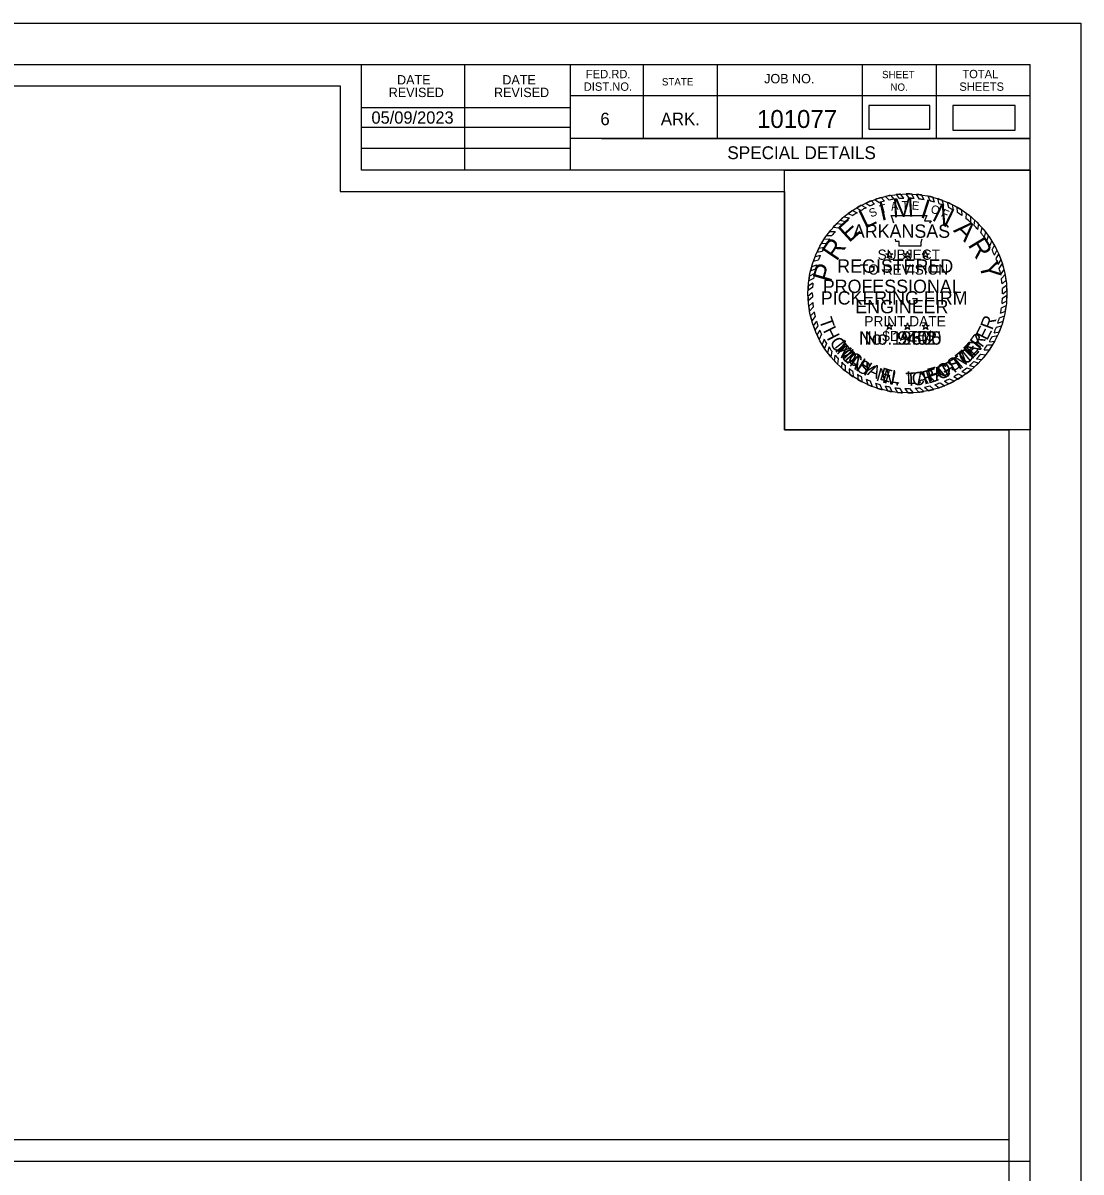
# Model space of a CAD drawing. Extents: x 1372039 to 1372773, y 376713 to 376926.
# Drawn here: x 1372673.7 to 1372772.8, y 376818.4 to 376926 of the extents above; entities that cross this region are included whole.
import ezdxf

# ---------------------------------------------------------------- set-up
doc = ezdxf.new("R2010")
doc.units = 0
for name, color, linetype in [('Default', 7, 'Continuous'), ('R_Border', 7, 'Continuous'), ('R_Border Notes', 7, 'Continuous'), ('R_Border Plan-Plan', 7, 'Continuous'), ('R_No Plot', 7, 'Continuous'), ('R_Revision Date Text', 7, 'Continuous'), ('STAMP_PE_CRAFTON', 7, 'Continuous'), ('STAMP_PE_FOSTER', 7, 'Continuous'), ('STAMP_PE_SEAL-INFO', 7, 'Continuous'), ('STAMP_PE_TAEGTMEYER', 7, 'Continuous'), ('STAMP_PE_TXT', 7, 'Continuous'), ('STAMP_PRELIMINARY', 7, 'Continuous')]:
    doc.layers.add(name, color=color, linetype=linetype)

msp = doc.modelspace()

# ---------------------------------------------------------------- linework, layer by layer
at = {"layer": 'Default'}
for points in [[(1372752.89, 376916.07), (1372758.6, 376916.07), (1372758.6, 376918.26), (1372752.89, 376918.26)], [(1372760.76, 376915.96), (1372766.59, 376915.96), (1372766.59, 376918.27), (1372760.76, 376918.27)]]:
    msp.add_lwpolyline(points, close=True, dxfattribs=at)
at = {"layer": 'R_Border'}
for p, q in [((1372451.83, 376922.11), (1372768.01, 376922.11)), ((1372705.37, 376912.23), (1372705.37, 376922.11)), ((1372715.05, 376912.23), (1372715.05, 376922.11)), ((1372724.91, 376922.11), (1372724.91, 376912.23)), ((1372731.75, 376922.11), (1372731.75, 376915.17)), ((1372738.69, 376922.11), (1372738.69, 376915.17)), ((1372752.27, 376922.11), (1372752.27, 376915.17)), ((1372759.21, 376922.11), (1372759.21, 376915.17)), ((1372768.01, 376716.65), (1372768.01, 376922.11)), ((1372768.01, 376919.17), (1372724.91, 376919.17)), ((1372768.01, 376919.19), (1372768.01, 376919.19)), ((1372705.37, 376918.09), (1372724.91, 376918.09)), ((1372705.37, 376916.23), (1372724.91, 376916.23)), ((1372768.01, 376915.17), (1372724.91, 376915.17)), ((1372727.87, 376915.17), (1372768.01, 376915.17)), ((1372705.37, 376914.29), (1372724.91, 376914.29)), ((1372768.01, 376912.23), (1372705.37, 376912.23))]:
    msp.add_line(p, q, dxfattribs=at)
at = {"layer": 'R_Border Plan-Plan'}
msp.add_line((1372451.83, 376819.38), (1372768.01, 376819.38), dxfattribs=at)
at = {"layer": 'R_No Plot'}
msp.add_line((1372439.43, 376926), (1372772.76, 376926), dxfattribs=at)
for points in [[(1372439.42, 376926), (1372772.76, 376926), (1372772.76, 376712.66), (1372439.42, 376712.66)], [(1372453.83, 376920.11), (1372703.37, 376920.11), (1372703.37, 376910.23), (1372720.91, 376910.23), (1372745.01, 376910.23), (1372745.01, 376887.89), (1372766.01, 376887.89), (1372766.01, 376718.65), (1372453.83, 376718.65)], [(1372766.01, 376821.38), (1372453.83, 376821.38), (1372453.83, 376920.11), (1372703.37, 376920.11), (1372703.37, 376910.23), (1372720.91, 376910.23), (1372745.01, 376910.23), (1372745.01, 376887.89), (1372766.01, 376887.89)], [(1372745.01, 376912.23), (1372768.01, 376912.23), (1372768.01, 376887.89), (1372745.01, 376887.89)]]:
    msp.add_lwpolyline(points, close=True, dxfattribs=at)
at = {"layer": 'STAMP_PE_SEAL-INFO'}
for p, q in [((1372752.62, 376909.14), (1372753.01, 376908.86)), ((1372753.12, 376909.36), (1372753.42, 376909.03)), ((1372753.47, 376909.48), (1372753.85, 376909.18)), ((1372754.06, 376909.67), (1372754.35, 376909.32)), ((1372754.45, 376909.76), (1372754.81, 376909.42)), ((1372754.93, 376909.86), (1372755.23, 376909.49)), ((1372755.45, 376909.93), (1372755.73, 376909.55)), ((1372756.18, 376909.58), (1372755.87, 376909.97)), ((1372756.68, 376909.58), (1372756.4, 376909.99)), ((1372757.14, 376909.56), (1372756.88, 376909.99)), ((1372757.65, 376909.51), (1372757.35, 376909.95)), ((1372758.07, 376909.45), (1372757.81, 376909.9)), ((1372758.63, 376909.33), (1372758.46, 376909.79)), ((1372759.04, 376909.22), (1372758.88, 376909.69)), ((1372759.49, 376909.07), (1372759.35, 376909.55)), ((1372759.91, 376908.91), (1372759.76, 376909.41)), ((1372760.37, 376908.71), (1372760.26, 376909.2)), ((1372750.93, 376908.17), (1372751.39, 376907.96)), ((1372751.35, 376908.43), (1372751.79, 376908.23)), ((1372751.74, 376908.68), (1372752.17, 376908.45)), ((1372752.19, 376908.93), (1372752.65, 376908.7)), ((1372760.81, 376908.48), (1372760.73, 376908.99)), ((1372761.2, 376908.25), (1372761.16, 376908.75)), ((1372761.63, 376907.96), (1372761.6, 376908.48)), ((1372762, 376907.7), (1372762.03, 376908.18)), ((1372749.87, 376907.22), (1372750.42, 376907.17)), ((1372750.21, 376907.54), (1372750.67, 376907.4)), ((1372750.55, 376907.84), (1372751.08, 376907.74)), ((1372754.99, 376907.96), (1372758.33, 376907.96)), ((1372755.11, 376907.65), (1372754.99, 376907.96)), ((1372755.21, 376907.36), (1372755.11, 376907.65)), ((1372755.22, 376907.24), (1372755.21, 376907.36)), ((1372758.33, 376907.96), (1372758.1, 376907.47)), ((1372758.1, 376907.47), (1372758.74, 376907.47)), ((1372758.74, 376907.47), (1372758.59, 376907.24)), ((1372762.44, 376907.33), (1372762.46, 376907.85)), ((1372762.75, 376907.03), (1372762.82, 376907.53)), ((1372763.11, 376906.66), (1372763.18, 376907.19)), ((1372748.93, 376906.09), (1372749.43, 376906.09)), ((1372749.21, 376906.46), (1372749.75, 376906.48)), ((1372749.55, 376906.87), (1372750.07, 376906.83)), ((1372763.39, 376906.34), (1372763.52, 376906.81)), ((1372763.71, 376905.93), (1372763.85, 376906.43)), ((1372763.93, 376905.61), (1372764.11, 376906.07)), ((1372748.22, 376904.92), (1372748.71, 376904.99)), ((1372748.45, 376905.35), (1372748.94, 376905.37)), ((1372748.69, 376905.75), (1372749.21, 376905.78)), ((1372755.41, 376905.53), (1372755.38, 376905.75)), ((1372755.72, 376905.53), (1372755.41, 376905.53)), ((1372755.72, 376905.1), (1372755.72, 376905.53)), ((1372757.75, 376905.1), (1372755.72, 376905.1)), ((1372757.77, 376905.44), (1372757.75, 376905.1)), ((1372757.85, 376905.75), (1372757.77, 376905.44)), ((1372764.24, 376905.11), (1372764.42, 376905.6)), ((1372764.44, 376904.75), (1372764.67, 376905.19)), ((1372747.69, 376903.69), (1372748.18, 376903.83)), ((1372747.84, 376904.1), (1372748.35, 376904.25)), ((1372748.03, 376904.53), (1372748.53, 376904.64)), ((1372764.67, 376904.26), (1372764.9, 376904.75)), ((1372764.81, 376903.93), (1372765.07, 376904.36)), ((1372765, 376903.38), (1372765.28, 376903.85)), ((1372747.43, 376902.78), (1372747.9, 376902.98)), ((1372747.54, 376903.19), (1372748.01, 376903.36)), ((1372765.11, 376903.01), (1372765.41, 376903.46)), ((1372765.25, 376902.45), (1372765.56, 376902.9)), ((1372747.65, 376901.64), (1372747.22, 376901.36)), ((1372747.71, 376902.08), (1372747.27, 376901.86)), ((1372747.8, 376902.54), (1372747.33, 376902.29)), ((1372765.31, 376902.07), (1372765.67, 376902.43)), ((1372765.38, 376901.56), (1372765.75, 376901.9)), ((1372747.62, 376901.22), (1372747.19, 376900.96)), ((1372747.6, 376900.73), (1372747.19, 376900.39)), ((1372765.41, 376901.15), (1372765.8, 376901.44)), ((1372765.41, 376900.22), (1372765.83, 376900.5)), ((1372765.43, 376900.63), (1372765.83, 376900.95)), ((1372747.61, 376900.32), (1372747.21, 376899.99)), ((1372747.64, 376899.82), (1372747.27, 376899.47)), ((1372765.32, 376899.33), (1372765.77, 376899.55)), ((1372765.37, 376899.72), (1372765.81, 376899.97)), ((1372747.69, 376899.39), (1372747.34, 376899.02)), ((1372747.77, 376898.93), (1372747.43, 376898.57)), ((1372747.86, 376898.52), (1372747.55, 376898.1)), ((1372765.13, 376898.38), (1372765.6, 376898.58)), ((1372765.23, 376898.83), (1372765.69, 376899.02)), ((1372747.99, 376898.07), (1372747.69, 376897.65)), ((1372748.13, 376897.65), (1372747.85, 376897.23)), ((1372764.84, 376897.5), (1372765.33, 376897.63)), ((1372764.98, 376897.88), (1372765.47, 376898.08)), ((1372748.29, 376897.22), (1372748.03, 376896.8)), ((1372748.47, 376896.84), (1372748.24, 376896.37)), ((1372748.7, 376896.38), (1372748.51, 376895.89)), ((1372764.2, 376896.15), (1372764.7, 376896.21)), ((1372764.47, 376896.65), (1372764.96, 376896.72)), ((1372764.63, 376896.99), (1372765.12, 376897.08)), ((1372748.94, 376895.97), (1372748.75, 376895.5)), ((1372749.14, 376895.66), (1372749.03, 376895.11)), ((1372749.42, 376895.27), (1372749.32, 376894.74)), ((1372763.69, 376895.38), (1372764.19, 376895.38)), ((1372764.03, 376895.87), (1372764.5, 376895.87)), ((1372749.72, 376894.89), (1372749.64, 376894.37)), ((1372750.03, 376894.56), (1372749.96, 376894.03)), ((1372750.35, 376894.23), (1372750.32, 376893.7)), ((1372762.74, 376894.29), (1372763.18, 376894.15)), ((1372762.99, 376894.55), (1372763.47, 376894.47)), ((1372763.38, 376894.98), (1372763.84, 376894.91)), ((1372750.69, 376893.92), (1372750.69, 376893.39)), ((1372751.05, 376893.62), (1372751.07, 376893.1)), ((1372751.39, 376893.37), (1372751.43, 376892.86)), ((1372751.82, 376893.09), (1372751.88, 376892.58)), ((1372761.26, 376893.13), (1372761.71, 376892.93)), ((1372761.6, 376893.35), (1372762.04, 376893.16)), ((1372762.06, 376893.7), (1372762.53, 376893.55)), ((1372762.33, 376893.92), (1372762.8, 376893.79)), ((1372752.17, 376892.89), (1372752.26, 376892.37)), ((1372752.65, 376892.64), (1372752.81, 376892.12)), ((1372753.02, 376892.47), (1372753.2, 376891.96)), ((1372753.51, 376892.28), (1372753.72, 376891.77)), ((1372753.92, 376892.14), (1372754.15, 376891.65)), ((1372754.43, 376892), (1372754.64, 376891.54)), ((1372754.83, 376891.92), (1372755.08, 376891.46)), ((1372758.11, 376891.9), (1372758.5, 376891.56)), ((1372758.61, 376892.01), (1372758.98, 376891.68)), ((1372759.07, 376892.13), (1372759.48, 376891.83)), ((1372759.56, 376892.29), (1372760, 376892.02)), ((1372759.98, 376892.46), (1372760.4, 376892.2)), ((1372760.44, 376892.67), (1372760.92, 376892.46)), ((1372760.84, 376892.88), (1372761.26, 376892.65)), ((1372755.33, 376891.84), (1372755.57, 376891.39)), ((1372755.77, 376891.79), (1372756.04, 376891.36)), ((1372756.25, 376891.76), (1372756.55, 376891.35)), ((1372756.71, 376891.76), (1372757.05, 376891.36)), ((1372757.23, 376891.79), (1372757.56, 376891.41)), ((1372757.67, 376891.83), (1372758.04, 376891.47))]:
    msp.add_line(p, q, dxfattribs=at)
for radius, start, end in [(9.32, 111.3124, 114.7026), (9.32, 105.2339, 109.0352), (8.91, 104.0352, 107.3615), (9.32, 99.7525, 102.7765), (8.91, 98.258, 101.0329), (9.32, 93.9381, 96.5517), (8.91, 92.1102, 95.0367), (9.32, 87.7298, 90.6707), (8.91, 85.9628, 88.9097), (9.32, 81.9732, 84.8236), (8.91, 79.9264, 82.696), (9.32, 75.3125, 77.9426), (8.91, 73.5575, 76.2314), (9.32, 69.6061, 72.3058), (9.32, 63.1329, 66.2704), (9.32, 123.6199, 126.5906), (8.91, 121.9746, 125.11), (9.32, 117.6544, 120.8099), (8.91, 115.6869, 119.1583), (8.91, 110.3086, 113.1659), (8.91, 67.6248, 70.504), (8.91, 61.1558, 64.3784), (9.32, 56.9003, 60.0942), (8.91, 54.9238, 58.2702), (9.32, 50.3492, 53.7159), (9.32, 135.4021, 138.3031), (8.91, 133.1331, 136.2562), (9.32, 129.7326, 132.5376), (8.91, 127.5297, 130.9683), (8.91, 48.3016, 52.0395), (8.91, 42.2212, 45.5512), (9.32, 44.3405, 47.3929), (9.32, 141.6056, 144.4486), (8.91, 139.301, 142.5873), (8.91, 36.135, 39.5311), (9.32, 38.1247, 41.2316), (9.32, 31.9614, 35.4294), (9.32, 152.864, 155.5189), (9.32, 147.0072, 149.899), (8.91, 151.0315, 153.573), (8.91, 145.0197, 148.2104), (8.91, 29.9032, 33.6645), (9.32, 25.9391, 29.0125), (9.32, 158.4077, 161.0701), (8.91, 156.3402, 159.2319), (8.91, 23.7732, 27.2211), (8.91, 17.6802, 21.4251), (9.32, 19.9538, 23.3141), (9.32, 164.3068, 166.894), (8.91, 162.4331, 165.0013), (8.91, 11.5444, 15.2364), (9.32, 13.8421, 17.4447), (9.32, 170.0003, 172.6878), (8.91, 173.73, 176.4734), (8.91, 167.9048, 170.9039), (8.91, 5.7599, 9.0606), (9.32, 7.5852, 10.8621), (9.32, 175.7409, 178.2066), (8.91, 179.6454, 182.2633), (8.91, 359.7329, 3.0639), (9.32, 1.7215, 4.7268), (9.32, 355.7156, 358.9569), (9.32, 181.7251, 184.1626), (9.32, 187.4204, 190.1927), (8.91, 185.4539, 188.234), (8.91, 353.8632, 357.1274), (9.32, 349.8305, 353.0885), (9.32, 193.0369, 195.9973), (8.91, 191.2274, 193.9858), (8.91, 341.777, 345.0925), (8.91, 348.0778, 351.3435), (9.32, 343.8925, 347.035), (9.32, 198.8967, 201.6281), (8.91, 196.9675, 199.8353), (8.91, 335.6038, 339.1858), (9.32, 337.3837, 340.9933), (9.32, 204.5479, 207.4328), (8.91, 202.7761, 205.4791), (8.91, 208.7883, 211.7934), (8.91, 329.5549, 333.2076), (9.32, 331.4037, 334.9332), (9.32, 210.8636, 213.6571), (9.32, 216.6115, 219.491), (8.91, 214.1838, 217.2747), (8.91, 323.5851, 327.4407), (9.32, 325.4405, 328.9872), (9.32, 222.48, 225.3801), (8.91, 220.3909, 223.3056), (8.91, 226.2494, 229.2407), (8.91, 310.7744, 314.3161), (9.32, 312.4518, 315.6633), (8.91, 316.6531, 320.3711), (9.32, 318.2846, 321.8043), (9.32, 228.3665, 231.348), (8.91, 232.229, 234.9336), (9.32, 234.295, 236.9452), (8.91, 238.2223, 240.8353), (8.91, 299.0768, 302.1724), (8.91, 304.823, 308.5143), (9.32, 306.3721, 310.208), (9.32, 240.1977, 242.8613), (8.91, 244.3204, 246.9486), (9.32, 246.576, 249.1558), (8.91, 250.3491, 253.1216), (8.91, 256.505, 259.1192), (8.91, 280.3459, 283.5814), (8.91, 286.6423, 289.9783), (9.32, 288.5709, 291.9733), (8.91, 292.8745, 296.1185), (9.32, 294.6481, 298.2166), (9.32, 300.621, 303.8703), (9.32, 252.5967, 255.3252), (9.32, 258.4433, 261.1398), (8.91, 262.3783, 265.2012), (9.32, 264.1978, 267.1009), (8.91, 268.3215, 271.277), (9.32, 270.2548, 273.3361), (8.91, 274.6157, 277.4486), (9.32, 276.4239, 279.4357), (9.32, 282.3199, 285.3702)]:
    msp.add_arc((1372756.51, 376900.67), radius, start, end, dxfattribs=at)
at = {"layer": 'STAMP_PE_TXT'}
for p, q in [((1372754.69, 376904.24), (1372754.49, 376904.39)), ((1372754.49, 376904.39), (1372754.74, 376904.39)), ((1372754.62, 376904.01), (1372754.69, 376904.24)), ((1372754.81, 376904.15), (1372754.62, 376904.01)), ((1372754.74, 376904.39), (1372754.81, 376904.62)), ((1372754.81, 376904.62), (1372754.89, 376904.39)), ((1372755.01, 376904.01), (1372754.81, 376904.15)), ((1372754.89, 376904.39), (1372755.14, 376904.39)), ((1372755.14, 376904.39), (1372754.94, 376904.24)), ((1372754.94, 376904.24), (1372755.01, 376904.01)), ((1372756.39, 376904.24), (1372756.19, 376904.39)), ((1372756.19, 376904.39), (1372756.44, 376904.39)), ((1372756.31, 376904.01), (1372756.39, 376904.24)), ((1372756.51, 376904.15), (1372756.31, 376904.01)), ((1372756.44, 376904.39), (1372756.51, 376904.62)), ((1372756.51, 376904.62), (1372756.59, 376904.39)), ((1372756.71, 376904.01), (1372756.51, 376904.15)), ((1372756.59, 376904.39), (1372756.83, 376904.39)), ((1372756.83, 376904.39), (1372756.64, 376904.24)), ((1372756.64, 376904.24), (1372756.71, 376904.01)), ((1372758.09, 376904.24), (1372757.89, 376904.39)), ((1372757.89, 376904.39), (1372758.13, 376904.39)), ((1372758.01, 376904.01), (1372758.09, 376904.24)), ((1372758.21, 376904.15), (1372758.01, 376904.01)), ((1372758.13, 376904.39), (1372758.21, 376904.62)), ((1372758.21, 376904.62), (1372758.29, 376904.39)), ((1372758.41, 376904.01), (1372758.21, 376904.15)), ((1372758.29, 376904.39), (1372758.53, 376904.39)), ((1372758.53, 376904.39), (1372758.33, 376904.24)), ((1372758.33, 376904.24), (1372758.41, 376904.01)), ((1372754.69, 376897.53), (1372754.49, 376897.68)), ((1372754.49, 376897.68), (1372754.74, 376897.68)), ((1372754.62, 376897.3), (1372754.69, 376897.53)), ((1372754.81, 376897.45), (1372754.62, 376897.3)), ((1372754.74, 376897.68), (1372754.81, 376897.91)), ((1372754.81, 376897.91), (1372754.89, 376897.68)), ((1372755.01, 376897.3), (1372754.81, 376897.45)), ((1372754.89, 376897.68), (1372755.14, 376897.68)), ((1372755.14, 376897.68), (1372754.94, 376897.53)), ((1372754.94, 376897.53), (1372755.01, 376897.3)), ((1372756.39, 376897.53), (1372756.19, 376897.68)), ((1372756.19, 376897.68), (1372756.44, 376897.68)), ((1372756.31, 376897.3), (1372756.39, 376897.53)), ((1372756.51, 376897.45), (1372756.31, 376897.3)), ((1372756.44, 376897.68), (1372756.51, 376897.91)), ((1372756.51, 376897.91), (1372756.59, 376897.68)), ((1372756.71, 376897.3), (1372756.51, 376897.45)), ((1372756.59, 376897.68), (1372756.83, 376897.68)), ((1372756.83, 376897.68), (1372756.64, 376897.53)), ((1372756.64, 376897.53), (1372756.71, 376897.3)), ((1372758.09, 376897.53), (1372757.89, 376897.68)), ((1372757.89, 376897.68), (1372758.13, 376897.68)), ((1372758.01, 376897.3), (1372758.09, 376897.53)), ((1372758.21, 376897.45), (1372758.01, 376897.3)), ((1372758.13, 376897.68), (1372758.21, 376897.91)), ((1372758.21, 376897.91), (1372758.29, 376897.68)), ((1372758.41, 376897.3), (1372758.21, 376897.45)), ((1372758.29, 376897.68), (1372758.53, 376897.68)), ((1372758.53, 376897.68), (1372758.33, 376897.53)), ((1372758.33, 376897.53), (1372758.41, 376897.3))]:
    msp.add_line(p, q, dxfattribs=at)
at = {"layer": 'STAMP_PRELIMINARY'}
msp.add_circle((1372756.51, 376900.67), 9.32, dxfattribs=at)

# ---------------------------------------------------------------- texts
at = {"layer": 'R_Border'}
for s, height, p in [('DATE', 0.879, (1372708.71, 376920.24)), ('DATE', 0.879, (1372718.57, 376920.24)), ('FED.RD.', 0.782, (1372726.39, 376920.83)), ('JOB NO.', 0.879, (1372743.09, 376920.35)), ('SHEET', 0.684, (1372754.13, 376920.83)), ('TOTAL', 0.782, (1372761.65, 376920.83)), ('REVISED', 0.879, (1372707.93, 376919.06)), ('REVISED', 0.879, (1372717.79, 376919.06)), ('DIST.NO.', 0.782, (1372726.19, 376919.65)), ('STATE', 0.684, (1372733.51, 376920.15)), ('NO.', 0.684, (1372754.91, 376919.65)), ('SHEETS', 0.782, (1372761.37, 376919.65)), ('6', 1.17, (1372727.75, 376916.43)), ('ARK.', 1.172, (1372733.41, 376916.43))]:
    msp.add_text(s, height=height, dxfattribs=at).set_placement(p)
at = {"layer": 'R_Border Notes'}
for s, height, p in [('101077', 1.68, (1372742.42, 376916.17)), ('SPECIAL DETAILS', 1.2, (1372739.64, 376913.25))]:
    msp.add_text(s, height=height, dxfattribs=at).set_placement(p)
at = {"layer": 'R_Revision Date Text'}
msp.add_text('05/09/2023', height=1.15, dxfattribs=at).set_placement((1372706.31, 376916.57))
at = {"layer": 'STAMP_PE_CRAFTON'}
for s, rotation, p in [('T', 310.7442, (1372749.48, 376895.57)), ('N', 49.2411, (1372762.79, 376894.69)), ('O', 317.6422, (1372750.15, 376894.76)), ('O', 41.8391, (1372761.95, 376893.91)), ('N', 324.4537, (1372750.99, 376893.97)), ('Y', 331.1686, (1372752.02, 376893.26)), ('F', 28.7821, (1372760.17, 376892.8)), ('T', 34.1136, (1372761.09, 376893.31)), ('N', 347.4752, (1372754.08, 376892.34)), ('C', 6.0117, (1372756.98, 376892.01)), ('R', 14.8189, (1372758.08, 376892.13)), ('A', 20.5125, (1372759.19, 376892.43)), ('.', 356.8926, (1372755.31, 376892.06))]:
    msp.add_text(s, height=1.25, rotation=rotation, dxfattribs=at).set_placement(p)
msp.add_text('No. 12370', height=1.25, dxfattribs=at).set_placement((1372751.97, 376895.87))
at = {"layer": 'STAMP_PE_FOSTER'}
for s, rotation, p in [('M', 308.339, (1372749.63, 376895.69)), ('E', 46.9613, (1372762.51, 376894.66)), ('R', 54.5031, (1372763.24, 376895.48)), ('I', 314.1842, (1372750.43, 376894.75)), ('T', 39.4194, (1372761.65, 376893.91)), ('C', 319.8733, (1372750.78, 376894.4)), ('H', 327.7235, (1372751.71, 376893.66)), ('O', 23.719, (1372759.59, 376892.75)), ('S', 31.7234, (1372760.7, 376893.28)), ('A', 335.7276, (1372752.69, 376893.08)), ('E', 343.5779, (1372753.83, 376892.61)), ('L', 350.8115, (1372754.89, 376892.34)), ('L', 1.2666, (1372756.43, 376892.18)), ('F', 15.8691, (1372758.55, 376892.42)), ('.', 6.8035, (1372757.47, 376892.24))]:
    msp.add_text(s, height=1.2, rotation=rotation, dxfattribs=at).set_placement(p)
msp.add_text('No. 9402', height=1.25, dxfattribs=at).set_placement((1372752.5, 376895.87))
at = {"layer": 'STAMP_PE_TAEGTMEYER'}
for s, rotation, p in [('T', 289.646, (1372748.21, 376898.18)), ('R', 69.57, (1372764.46, 376897.18)), ('H', 296.7339, (1372748.57, 376897.2)), ('E', 63.0984, (1372763.96, 376896.2)), ('O', 303.7708, (1372749.16, 376896.09)), ('Y', 53.9986, (1372763.29, 376895.26)), ('M', 314.2033, (1372749.81, 376895.14)), ('M', 39.3, (1372761.51, 376893.57)), ('E', 46.8094, (1372762.55, 376894.45)), ('A', 321.0594, (1372750.78, 376894.17)), ('S', 327.8239, (1372751.6, 376893.53)), ('G', 23.3052, (1372759.51, 376892.53)), ('T', 31.466, (1372760.61, 376893.02)), ('N', 344.2727, (1372753.5, 376892.52)), ('T', 3.0061, (1372756.38, 376891.99)), ('A', 8.9826, (1372757.42, 376892.05)), ('E', 17.6836, (1372758.46, 376892.2)), ('.', 350.6464, (1372754.71, 376892.19))]:
    msp.add_text(s, height=1.25, rotation=rotation, dxfattribs=at).set_placement(p)
msp.add_text('No. 19605', height=1.25, dxfattribs=at).set_placement((1372751.97, 376895.87))
at = {"layer": 'STAMP_PE_TXT'}
for s, rotation, p in [('A', 9.0679, (1372755, 376908.4)), ('T', 1.8248, (1372755.98, 376908.53)), ('E', 355.2002, (1372756.89, 376908.54)), ('S', 23.5541, (1372753.11, 376907.77)), ('T', 16.311, (1372754.03, 376908.15)), ('O', 342.2506, (1372758.62, 376908.26)), ('F', 335.0075, (1372759.59, 376907.92))]:
    msp.add_text(s, height=0.781, rotation=rotation, dxfattribs=at).set_placement(p)
for s, p in [('ARKANSAS', (1372751.4, 376905.88)), ('REGISTERED', (1372749.93, 376902.61)), ('PROFESSIONAL', (1372748.58, 376900.71)), ('ENGINEER', (1372751.62, 376898.81))]:
    msp.add_text(s, height=1.25, dxfattribs=at).set_placement(p)
at = {"layer": 'STAMP_PRELIMINARY'}
for s, rotation, p in [('I', 12.5248, (1372754.05, 376907.46)), ('M', 3.1074, (1372755.15, 376907.77)), ('I', 342.3164, (1372757.62, 376907.83)), ('L', 25.513, (1372752.52, 376906.7)), ('N', 333.9382, (1372758.72, 376907.56)), ('E', 42.3578, (1372751.04, 376905.37)), ('A', 315.6579, (1372760.76, 376906.53)), ('R', 301.3831, (1372762.13, 376905.22)), ('R', 56.2292, (1372749.88, 376903.63)), ('Y', 283.2593, (1372763.21, 376903.43)), ('P', 73.913, (1372749.33, 376901.61))]:
    msp.add_text(s, height=1.8, rotation=rotation, dxfattribs=at).set_placement(p)
for s, height, p in [('SUBJECT', 0.96, (1372753.71, 376903.82)), ('TO REVISION', 0.96, (1372752.05, 376902.43)), ('PICKERING FIRM', 1.25, (1372748.39, 376899.63)), ('PRINT DATE', 0.96, (1372752.47, 376897.59)), ('$DATE$', 0.96, (1372754.15, 376896.2))]:
    msp.add_text(s, height=height, dxfattribs=at).set_placement(p)

doc.saveas('drawing.dxf')
